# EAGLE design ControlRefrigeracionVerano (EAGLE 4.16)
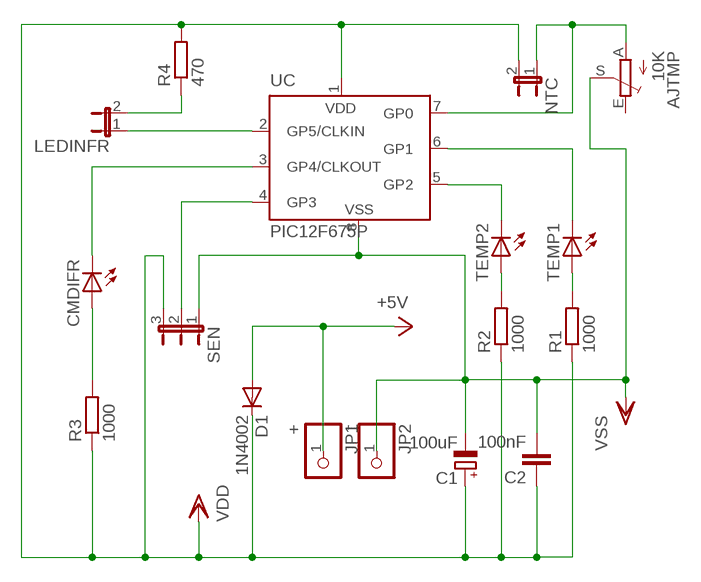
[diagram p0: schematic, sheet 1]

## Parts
AJTMP  10K  TRIM_EU-ST10  [ST10]
C1  100uF  CPOL-EUE5-6  [E5-6]
C2  100nF  C-EU050-024X044  [C050-024X044]
CMDIFR  LED3MM  [LED3MM]
D1  1N4002  1N4004  [DO41-10]
JP1  +  PINHD-1X1  [1X01]
JP2  -  PINHD-1X1  [1X01]
LEDINFR  JP1E  [JP1]
NTC  JP1E  [JP1]
R1  1000  R-EU_0207/10  [0207/10]
R2  1000  R-EU_0207/10  [0207/10]
R3  1000  R-EU_0207/10  [0207/10]
R4  470  R-EU_0207/10  [0207/10]
SEN  JP2E  [JP2]
TEMP1  LED3MM  [LED3MM]
TEMP2  LED3MM  [LED3MM]
UC  PIC12F675P  [DIL8]

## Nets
+5V: D1.A JP1.1
N$1: R2.2 TEMP2.A
N$2: R1.2 TEMP1.A
N$3: CMDIFR.A R3.2
N$4: TEMP2.K(C) UC.5(GP2)
N$5: SEN.2 UC.4(GP3)
N$6: CMDIFR.K(C) UC.3(GP4/CLKOUT)
N$7: LEDINFR.1 UC.2(GP5/CLKIN)
N$8: TEMP1.K(C) UC.6(GP1)
N$9: LEDINFR.2 R4.1
N$13: AJTMP.A NTC.1 UC.7(GP0)
VDD: C1.+ C2.1 D1.C NTC.2 R1.1 R2.1 R3.1 R4.2 SEN.3 UC.1(VDD)
VSS: AJTMP.S C1.- C2.2 JP2.1 SEN.1 UC.8(VSS)
Unconnected: AJTMP.E

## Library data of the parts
AJTMP = pot:TRIM_EU-: POTENTIOMETER
C1 = rcl:CPOL-EU: POLARIZED CAPACITOR, European symbol
C2 = rcl:C-EU: CAPACITOR, European symbol
CMDIFR TEMP1 TEMP2 = led:LED: LED
D1 = diode:1N4004: DIODE
JP1 JP2 = pinhead:PINHD-1X1: PIN HEADER
LEDINFR NTC = jumper:JP1E: JUMPER
R1-R4 = rcl:R-EU_: RESISTOR, European symbol
SEN = jumper:JP2E: JUMPER
UC = microchip:PIC12F6*: Data Sheet 8-Pin FLASH-Based 8-Bit CMOS Microcontrollers Source: http://www.microchip.com .. 41190c.pdf

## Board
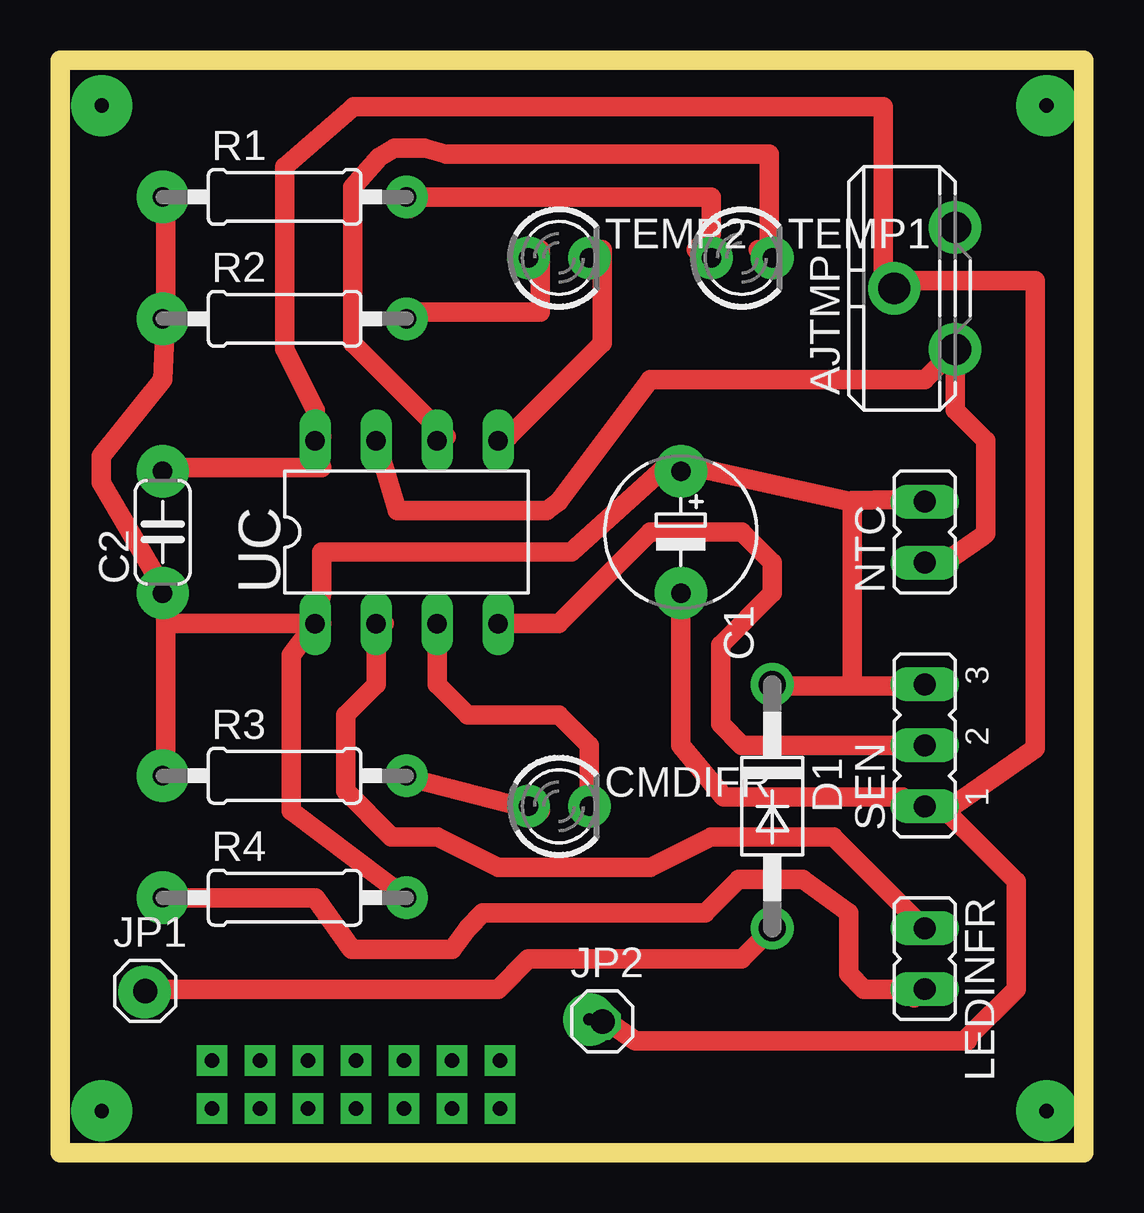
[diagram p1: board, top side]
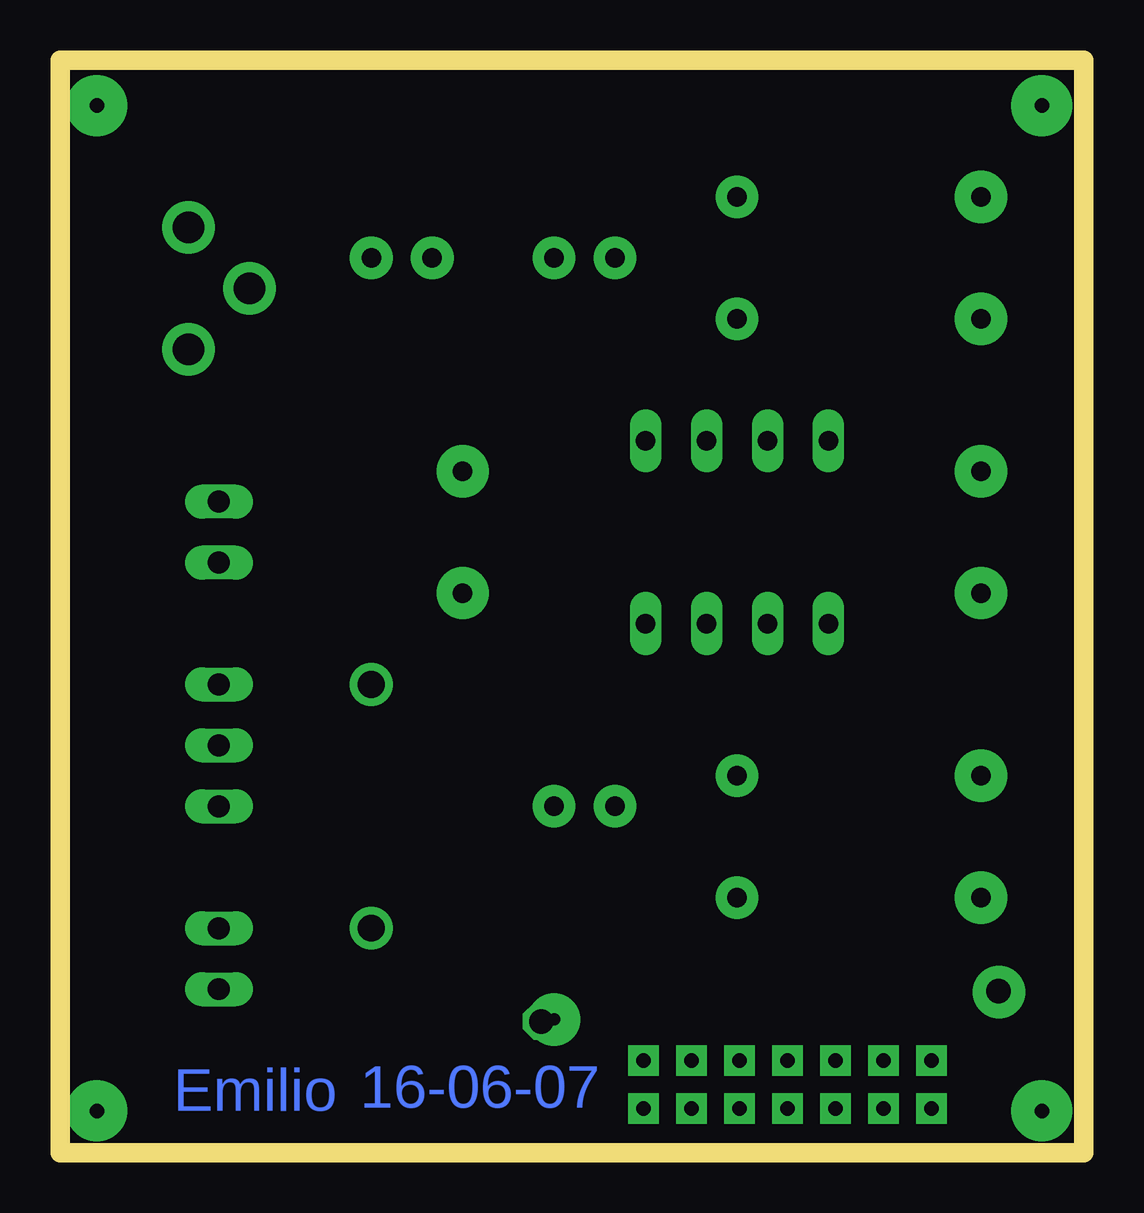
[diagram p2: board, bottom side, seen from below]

Size 42.65 x 45.55 mm. Coordinates in mm from the lower left corner, seen from the top.
Outline: 0,0 42.65,0 42.65,45.55 0,45.55 0,0
Copper layers (1*16): Top 0.035mm / dielectric 1.5mm / Bottom 0.035mm
Design rules "default": minimum track width 12mil, minimum drill 12mil, track to track 10mil, track to pad 10mil, pad to pad 10mil, via to via 10mil, smd to smd 8mil, copper to edge 40mil, drill to drill 2mil, minimum pad ring 10mil, minimum via ring 8mil, stop-mask expansion 4mil, vias tented up to drill 0mil, thermal gap 10mil

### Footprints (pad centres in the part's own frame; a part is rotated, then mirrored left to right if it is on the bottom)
ST10 = drill 1.321 octagon: A -2.54,-1.27; E 2.54,-1.27; S 0,1.27
E5-6 = drill 0.813 pad 1.905 round: + -2.54,0 | drill 0.813 pad 1.905 octagon: - 2.54,0
C050-024X044 = drill 0.813 octagon: 1 -2.54,0; 2 2.54,0
LED3MM = drill 0.813 octagon: A -1.27,0; K 1.27,0
DO41-10 = drill 1.118 round: A 5.08,0; C -5.08,0
1X01 = drill 1.016 octagon: 1 0,0
JP1 = drill 0.914 long: 1 0,-1.27; 2 0,1.27
0207/10 = drill 0.813 octagon: 1 -5.08,0; 2 5.08,0
JP2 = drill 0.914 long: 1 -2.54,0; 2 0,0; 3 2.54,0
DIL8 = drill 0.813 long: 1 -3.81,-3.81; 2 -1.27,-3.81; 3 1.27,-3.81; 4 3.81,-3.81; 5 3.81,3.81; 6 1.27,3.81; 7 -1.27,3.81; 8 -3.81,3.81

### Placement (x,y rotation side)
AJTMP  36.03,36.03 90 top
C1  25.87,25.88 270 top
C2  4.28,25.88 90 top
CMDIFR  20.79,14.45 0 top
D1  29.68,14.45 270 top
JP1  3.55,6.74 0 top
JP2  22.6,5.48 0 top
LEDINFR  36.03,8.09 180 top
NTC  36.03,25.88 0 top
R1  9.36,39.84 0 top
R2  9.36,34.77 0 top
R3  9.36,15.71 0 top
R4  9.36,10.63 0 top
SEN  36.03,16.98 90 top
TEMP1  28.41,37.3 0 top
TEMP2  20.79,37.3 0 top
UC  14.44,25.88 0 top

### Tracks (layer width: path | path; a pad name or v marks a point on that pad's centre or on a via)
+5V
  Top 0.813: D1.A 28.41,8.09 19.52,8.09 18.25,6.82 3.52,6.82 3.52,6.78 JP1.1
N$1
  Top 0.813: R2.2 14.8,35.05 20,35.05 20,37.66 TEMP2.A
N$2
  Top 0.813: 14.55,39.37 R1.2 27.14,39.84 27.14,38.3 26.5,37.66 TEMP1.A
N$3
  Top 0.813: CMDIFR.A 20,14.25 19.88,14.25 14.8,15.55 R3.2
N$4
  Top 0.813: UC.5 18.7,29.85 22.6,33.75 22.6,37.66 TEMP2.K
N$5
  Top 0.813: UC.4 20.79,22.06 24.6,25.88 28.41,25.88 29.68,24.6 29.68,23.34 27.52,21.18 27.52,17.87 28.41,16.98 SEN.2
N$6
  Top 0.813: UC.3 15.71,19.52 16.98,18.25 20.79,18.25 22.06,16.98 CMDIFR.K
N$7
  Top 0.813: UC.2 13.5,22.05 13.17,21.73 13.17,19.52 11.9,18.25 11.9,15.08 13.8,13.17 15.71,13.17 18.25,11.91 24.6,11.91 27.14,13.17 32.22,13.17 LEDINFR.1
N$8
  Top 0.813: UC.6 16.1,29.85 12.2,33.75 12.2,40.25 13.3,41.5 13.93,41.88 15.2,41.88 16.09,41.62 29.55,41.62 29.55,37.56 TEMP1.K 29.1,37.66
N$9
  Top 0.813: R4.1 4.4,10.35 4.68,10.63 10.63,10.63 12.15,8.48 16.34,8.48 16.98,9.36 17.61,10 26.89,10 28.28,11.4 30.95,11.4 32.86,10 32.86,7.46 33.49,6.82 LEDINFR.2 35.6,6.45
N$10  (via drill 0.6 pad 1.27)
  other vias: 8.33,1.84
N$11  (via drill 0.6 pad 1.27)
  other vias: 10.33,1.84
N$12  (via drill 0.6 pad 1.27)
  other vias: 12.33,1.84
N$13
  Top 0.813: NTC.1 36.9,24.66 38.45,25.7 38.57,25.82 38.57,29.68 37.3,30.95 AJTMP.A 36.03,32.22 24.6,32.22 20.79,27.14 20.28,26.76 14.06,26.76 UC.7
N$14  (via drill 0.6 pad 1.27)
  other vias: 14.33,1.84
N$15  (via drill 0.6 pad 1.27)
  other vias: 16.33,1.84
N$16  (via drill 0.6 pad 1.27)
  other vias: 18.33,1.84
N$17  (via drill 0.6 pad 1.27)
  other vias: 6.33,1.84
N$18  (via drill 0.6 pad 1.27)
  other vias: 16.33,3.84
N$19  (via drill 0.6 pad 1.27)
  other vias: 14.33,3.84
N$20  (via drill 0.6 pad 1.27)
  other vias: 12.33,3.84
N$21  (via drill 0.6 pad 1.27)
  other vias: 10.33,3.84
N$22  (via drill 0.6 pad 1.27)
  other vias: 8.33,3.84
N$23  (via drill 0.6 pad 1.27)
  other vias: 6.33,3.84
N$24  (via drill 0.6 pad 1.27)
  other vias: 18.33,3.84
N$25  (via drill 0.6 pad 2.54)
  other vias: 1.74,43.66
N$26  (via drill 0.6 pad 2.54)
  other vias: 41.11,43.66
N$27  (via drill 0.6 pad 2.54)
  other vias: 1.74,1.74
N$28  (via drill 0.6 pad 2.54)
  other vias: 41.11,1.74
N$29  (via drill 0.5 pad 2.18)
  other vias: 4.28,28.41
N$30  (via drill 0.5 pad 2.18)
  other vias: 4.28,23.34
N$31  (via drill 0.5 pad 2.18)
  other vias: 4.28,34.77
N$32  (via drill 0.5 pad 2.18)
  other vias: 4.28,39.84
N$33  (via drill 0.5 pad 2.18)
  other vias: 4.28,15.71 3.52,6.7
N$34  (via drill 0.5 pad 2.18)
  other vias: 4.28,10.63
N$35  (via drill 0.5 pad 2.18)
  other vias: 22.06,5.55
N$36  (via drill 0.5 pad 1.78)
  other vias: 14.44,10.63
N$37  (via drill 0.5 pad 1.78)
  other vias: 14.44,15.71
N$38  (via drill 0.5 pad 1.78)
  other vias: 19.52,14.45
N$39  (via drill 0.5 pad 1.78)
  other vias: 22.06,14.45
N$40  (via drill 0.5 pad 1.78)
  other vias: 29.68,9.36
N$41  (via drill 0.5 pad 1.78)
  other vias: 29.68,19.52
N$42  (via drill 0.5 pad 2.18)
  other vias: 25.87,28.41
N$43  (via drill 0.5 pad 2.18)
  other vias: 34.76,36.03
N$44  (via drill 0.5 pad 2.18)
  other vias: 37.3,38.58
N$45  (via drill 0.5 pad 2.18)
  other vias: 37.3,33.5
N$46  (via drill 0.5 pad 2.18)
  other vias: 25.87,23.34
N$47  (via drill 0.5 pad 1.78)
  other vias: 14.44,39.84
N$48  (via drill 0.5 pad 1.78)
  other vias: 14.44,34.77
N$49  (via drill 0.5 pad 1.78)
  other vias: 19.52,37.3
N$50  (via drill 0.5 pad 1.78)
  other vias: 22.06,37.3
N$51  (via drill 0.5 pad 1.78)
  other vias: 27.14,37.3
N$52  (via drill 0.5 pad 1.78)
  other vias: 29.68,37.3
VDD
  Top 0.813: 33,19.45 30.4,19.45 D1.C | 33,19.45 35.6,19.45 SEN.3 | 33,27.13 33,19.45 | 33,27.13 33,27.2 35.6,27.25 NTC.2 | 33,27.13 26.5,28.55 C1.+ 25.2,28.55 21.3,25.04 10.9,25.04 10.9,23.35 UC.1 | 4.4,35.05 4.4,40.25 R1.1 | 4.4,22.05 4.4,23.35 | 4.4,22.05 4.4,15.55 R3.1 | 4.4,22.05 10.9,22.05 UC.1 | R4.2 14.8,10.35 9.63,14.25 9.63,20.75 UC.1 | 4.4,23.35 1.72,27.93 1.72,29.03 4.28,32.22 4.4,35.05 | 4.4,35.05 R2.1 | 4.4,23.35 C2.1
VSS
  Top 0.813: C2.2 4.4,28.55 10.9,28.55 UC.8 | JP2.1 22.6,5.16 | 36.9,14.25 40.64,16.85 40.64,36.36 35.6,36.36 AJTMP.S 34.3,36.36 34.3,43.62 12.23,43.62 9.36,41.11 9.36,33.5 10.63,30.95 UC.8 | 36.9,14.25 SEN.1 35.6,14.25 35.09,14.83 27.65,14.83 25.87,16.98 C1.- | UC.8 10.9,29.85 | 36.9,14.25 39.84,11.31 39.84,6.82 37.81,4.79 37.81,4.67 23.96,4.67 22.31,5.81 JP2.1 | 22.57,5.43 22.6,5.46 JP2.1

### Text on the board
Bottom: 16-06-07 | Emilio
